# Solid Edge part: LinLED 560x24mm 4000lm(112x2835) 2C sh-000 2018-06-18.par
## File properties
Subject: LinLED 560x24mm 4000lm(112x2835) 2C
Author: radoslaw.kuczynski
Template: iso metric part.par
Last saved by: radoslaw.kuczynski
Revision: 2
Application: Solid Edge
Username: radoslaw.kuczynski
Gęstość: 0,000 kg/m^3
Dokładność: 0,990
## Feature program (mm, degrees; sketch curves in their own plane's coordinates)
body "unnamed Body 1"
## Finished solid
Body 1: solid body, 2434 faces, 6315 edges, 4133 vertices, 3 separate solids.
  Faces by surface: plane 2104, cylinder 147, spline 96, cone 30, swept 23, sphere 16, torus 10, spun 8
  Edges by curve: line 5619, curve on surface 360, circle 206, ellipse 66, spline 60, intersection 4
Bounding box of the edges (mm; curved faces can reach further): 560.000 x 4.500 x 24.000, from (-280, -3.5, -12) to (280, 1, 12).
Cylindrical faces by radius (mm): R0.2 x46, R0.2169 x6, R0.25 x20, R0.3373 x6, R0.4 x8, R0.4006 x2, R0.4008 x2, R0.525 x2, R0.6 x20, R0.75 x1, R1 x8, R1.1 x4, R1.2 x10, R2.15 x12
Conical faces (half-angle, radius in mm at the cone's reference point): 0.5 deg R0.5056 x4, 0.5 deg R1.0082 x4, 1 deg R0.5511 x2, 10 deg R0.2132 x4, 10 deg R0.4132 x4, 18.8604 deg R1.0669 x4, 27.363 deg R0.6214 x2, 45 deg R0.575 x2, 45 deg R0.625 x4
Toroidal faces (ring radius, tube radius in mm): R0.8 r0.2 x4, R0.8522 r0.3 x2, R0.9002 r0.2 x2, R0.9018 r0.2 x2
Spherical faces by radius (mm): R0.2 x12, R0.6 x4
Planar faces by outward normal: +x 259, +y 13, +z 267, -x 259, -y 379, -z 273, oblique 654
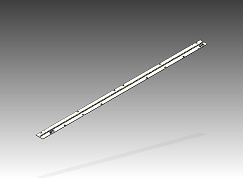
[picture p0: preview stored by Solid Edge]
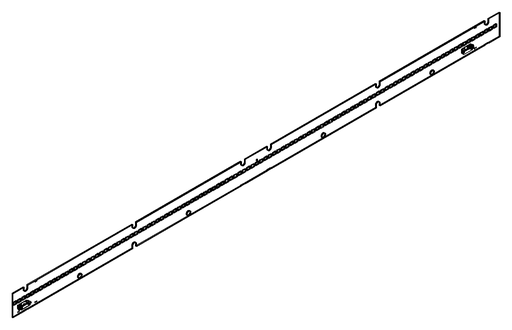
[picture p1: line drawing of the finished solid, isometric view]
